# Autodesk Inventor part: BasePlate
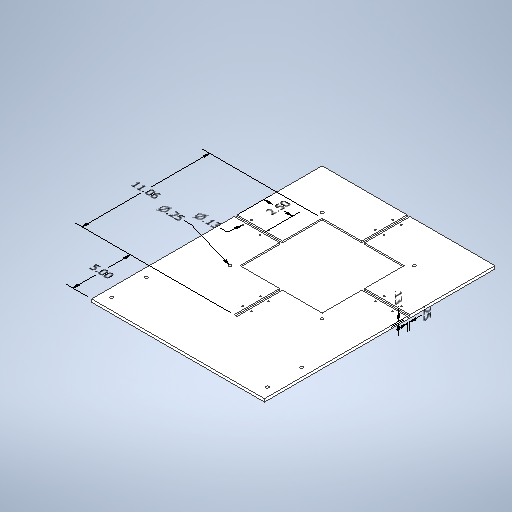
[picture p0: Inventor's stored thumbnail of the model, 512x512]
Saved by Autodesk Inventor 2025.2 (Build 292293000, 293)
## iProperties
Created: 2025-09
Part Number: BasePlate
Material: Generic
Document SubType Name: Modeling
Designer: tyler
Density: 1 g/cm^3
Appearance: Default
Author: tyler
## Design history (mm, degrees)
node "Annotations"
  node "Diameter Dimension 1" dims "d8" = 381, "d9" = 381, "d10" = 180.975, "d11" = 180.975, "d12" = 3.175, "d13" = 3.175, "d22" = 360 deg (derived), "d50" = 6.35 (derived)
  node "Diameter Dimension 2" dims "d8" = 381, "d9" = 381, "d10" = 180.975, "d11" = 180.975, "d12" = 3.175, "d13" = 3.175, "d22" = 360 deg (derived), "d52" = 3.175 (derived)
  node "Linear Dimension 1" dims "d8" = 381, "d9" = 381, "d10" = 180.975, "d11" = 180.975, "d12" = 3.175, "d13" = 3.175, "d22" = 360 deg (derived), "d55" = 3.175 (derived)
  node "Linear Dimension 2" dims "d8" = 381, "d9" = 381, "d10" = 180.975, "d11" = 180.975, "d12" = 3.175, "d13" = 3.175, "d22" = 360 deg (derived), "d58" = 6.35 (derived)
  node "Linear Dimension 3" dims "d8" = 381, "d9" = 381, "d10" = 180.975, "d11" = 180.975, "d12" = 3.175, "d13" = 3.175, "d22" = 360 deg (derived), "d60" = 63.5 (derived)
  node "Linear Dimension 4" dims "d8" = 381, "d9" = 381, "d10" = 180.975, "d11" = 180.975, "d12" = 3.175, "d13" = 3.175, "d22" = 360 deg (derived), "d74" = 127 (derived)
  node "Linear Dimension 5" dims "d8" = 381, "d9" = 381, "d10" = 180.975, "d11" = 180.975, "d12" = 3.175, "d13" = 3.175, "d22" = 360 deg (derived), "d78" = 280.9875 (derived)
sketch "Sketch1"
  geometry: L1 (190.5, 254)-(-190.5, 254); L2 (-190.5, 254)-(-190.5, -254); L3 (-190.5, -254)-(190.5, -254); L4 (190.5, -254)-(190.5, 254); L5 (190.5, 254)-(-190.5, -254); L6 (-190.5, 254)-(190.5, -254); L7 (-190.5, -254)-(190.5, -254); L8 (190.5, -254)-(190.5, 127); L9 (-190.5, 127)-(-190.5, -254); L10 (88.9, -152.4)-(-88.9, -152.4); L11 (-88.9, -152.4)-(-88.9, 25.4); L12 (-88.9, 25.4)-(88.9, -152.4); L13 (88.9, 25.4)-(-88.9, -152.4); 2 further points
  constraints: 26 end point, 4 midpoint, 3 parallel, 2 horizontal, 2 perpendicular
  dimensions: "d0" = 381 distance of L3.end L2.end; "d1" = 508 distance of L2.end L1.end; "d3" = 381 distance of L8.end L7.end
extrude "Extrusion1" new body sketch "Sketch1" distance "d6" = 6.35; taper "d7" = 0 deg
sketch "Sketch2"
  geometry: L1 (190.5, -254)-(190.5, 254) reference; L2 (190.5, 254)-(-190.5, 254); L3 (-190.5, 254)-(-190.5, -127); L4 (-190.5, -127)-(190.5, -127); L5 (190.5, -127)-(190.5, 254); L6 (-190.5, 254)-(-190.5, 63.5); L7 (90.487, -26.988)-(-90.487, -26.988); L8 (-90.487, -26.988)-(-90.487, 153.987); L9 (-90.487, 153.987)-(90.487, 153.987); L10 (90.487, 153.987)-(90.487, -26.988); L11 (90.487, -26.988)-(-90.487, 153.987); L12 (-90.487, -26.988)-(90.487, 153.987); L13 (-90.487, 63.5)-(-90.487, 66.675); L14 (-90.487, 63.5)-(-90.487, 60.325); L15 (-90.487, 60.325)-(-190.5, 60.325); L16 (-90.487, 63.5)-(-190.5, 63.5); L17 (-90.487, 66.675)-(-190.5, 66.675); L18 (3.175, -26.988)-(3.175, -127); L19 (-3.175, -26.988)-(-3.175, -127); L20 (90.487, 66.675)-(190.5, 66.675); L21 (90.487, 60.325)-(190.5, 60.325); L22 (-3.175, 153.987)-(-3.175, 254); L23 (3.175, 153.987)-(3.175, 254); 16 further points
  constraints: 44 end point, 5 perpendicular, 4 midpoint, 4 parallel, 4 point on line, 2 horizontal, 25 other
  dimensions: "d8" = 381 distance of L4.end L3.end; "d9" = 381 distance of L3.end L2.end; "d10" = 180.975 distance of L8.end L9.end; "d11" = 180.975 distance of L7.end L8.end; "d12" = 3.175 distance of L13.start L13.end; "d13" = 3.175 distance of L13.start L14.end; "d22" = 360 deg dimension on point (0, 63.5) L14.end (derived)
extrude "Extrusion2" cut sketch "Sketch2" distance "d18" = 3.175; taper "d19" = 0 deg
sketch "Sketch3" dims "d28" = 12.7
  geometry: L1 (-190.5, 60.325)-(-190.5, 66.675) reference; L2 (-190.5, 63.5)-(0, 63.5); L3 (101.6, 165.1)-(-101.6, 165.1); L4 (-101.6, 165.1)-(-101.6, -38.1); L5 (-101.6, -38.1)-(101.6, -38.1); L6 (101.6, -38.1)-(101.6, 165.1); L7 (101.6, 165.1)-(-101.6, -38.1); L8 (-101.6, 165.1)-(101.6, -38.1); L9 (-107.95, -38.1)-(-107.95, 165.1); L10 (-101.6, 171.45)-(101.6, 171.45); L11 (107.95, 165.1)-(107.95, -38.1); L12 (101.6, -44.45)-(-101.6, -44.45); L13 (-107.95, 60.325)-(-120.65, 60.325); L14 (-90.487, 60.325)-(-190.5, 60.325) reference; L15 (-120.65, 60.325)-(-171.45, 60.325); L16 (-171.45, 60.325)-(-171.45, 47.625); L17 (-171.45, 47.625)-(-120.65, 47.625); L18 (-120.65, 47.625)-(-120.65, 60.325); L19 (-120.65, 66.675)-(-171.45, 66.675); L20 (-171.45, 66.675)-(-171.45, 79.375); L21 (-171.45, 79.375)-(-120.65, 79.375); L22 (-120.65, 79.375)-(-120.65, 66.675); L23 (-120.65, 60.325)-(-133.35, 47.625); L24 (-171.45, 60.325)-(-158.75, 47.625); L25 (-120.65, 66.675)-(-133.35, 79.375); L26 (-171.45, 66.675)-(-158.75, 79.375); C1 r 1.587 at (-127, 53.975); C2 r 1.587 at (-165.1, 53.975); C3 r 1.587 at (-127, 73.025); C4 r 1.587 at (-165.1, 73.025); C5 r 3.175 at (101.6, -38.1); C6 r 3.175 at (-101.6, -38.1); C7 r 3.175 at (-101.6, 165.1); C8 r 3.175 at (101.6, 165.1); C9 r 1.587 at (9.525, -63.5); C10 r 1.587 at (-9.525, -63.5); C11 r 1.587 at (-9.525, -101.6); C12 r 1.587 at (9.525, -101.6); C13 r 1.587 at (127, 73.025); C14 r 1.587 at (127, 53.975); C15 r 1.587 at (165.1, 53.975); C16 r 1.587 at (165.1, 73.025); C17 r 1.587 at (-9.525, 190.5); C18 r 1.587 at (9.525, 190.5); C19 r 1.587 at (9.525, 228.6); C20 r 1.587 at (-9.525, 228.6); A1 r 6.35 centre (-101.6, -38.1) between (-107.95, -38.1) and (-101.6, -44.45); A2 r 6.35 centre (-101.6, 165.1) between (-107.95, 165.1) and (-101.6, 171.45); A3 r 6.35 centre (101.6, -38.1) between (107.95, -38.1) and (101.6, -44.45); 2 further points
  constraints: 48 end point, 23 centre point, 8 coincident, 8 parallel, 8 point on line, 7 midpoint, 6 point on circle, 5 horizontal, 4 perpendicular, 2 tangent, 1 vertical alignment, 35 other
  dimensions: "d24" = 203.2 distance of L5.end L4.end; "d25" = 203.2 distance of L4.end L3.end; "d26" = 12.7 diameter of A1; "d27" = 12.7 diameter of A2; "d29" = 12.7 diameter of A3; "d30" = 12.7 distance of L13.start L13.end; "d31" = 50.8 distance of L17.end L16.end; "d32" = 12.7 distance of L16.end L15.end; "d33" = 50.8 distance of L20.end L21.end; "d34" = 12.7 distance of L19.end L20.end; "d35" = 3.175 diameter of C1; "d36" = 3.175 diameter of C2; "d37" = 3.175 diameter of C3; "d38" = 3.175 diameter of C4; "d39" = 6.35 diameter of C5; "d40" = 6.35 diameter of C6; "d41" = 6.35 diameter of C7; "d42" = 6.35 diameter of C8; "d45" = 360 deg dimension on L2.end C1.centre (derived)
extrude "Extrusion3" cut sketch "Sketch3" distance "d47" = 6.35; taper "d48" = 0 deg
sketch "Sketch4"
  geometry: L1 (-190.5, 254)-(-190.5, -254) reference; L2 (-190.5, -254)-(-190.5, -247.65); L3 (-190.5, -247.65)-(-184.15, -247.65); L4 (-184.15, -247.65)-(-184.15, -52.726); L5 (-184.15, -247.65)-(0, -247.65); L6 (0, -247.65)-(0, -127.291); L7 (-184.15, -247.65)-(-184.15, -228.6); L8 (-184.15, -228.6)-(-171.45, -228.6); L9 (-184.15, -228.6)-(-184.15, -187.96); L10 (-184.15, -127.291)-(-184.15, -152.691); L11 (-184.15, -152.691)-(-171.45, -152.691); L12 (-190.5, -254)-(190.5, -254) reference; C1 r 3.175 at (-171.45, -228.6); C2 r 3.175 at (-171.45, -152.691); C3 r 3.175 at (171.45, -228.6); C4 r 3.175 at (171.45, -152.691); 1 further point
  constraints: 20 end point, 5 perpendicular, 5 point on line, 4 centre point, 2 coincident, 2 symmetric about line, 1 horizontal, 2 other
  dimensions: "d61" = 6.35 distance of L1.end L2.end; "d62" = 6.35 distance of L2.end L3.end; "d63" = 19.05 distance of L3.end L7.end; "d64" = 12.7 distance of L7.end L8.end; "d67" = 25.4 distance of L10.start L10.end; "d68" = 6.35 diameter of C1; "d69" = 6.35 diameter of C2; "d75" = 25.4 distance from line of L12 C3.centre (derived)
extrude "Extrusion4" cut sketch "Sketch4" distance "d70" = 25.4; taper "d71" = 0 deg
body "Solid1"
node "Sketch Circular Pattern2" dims "d22" = 360 deg (derived)
node "Sketch Circular Pattern3" dims "d45" = 360 deg (derived)
other parameters: "d49" = 0.10935 (derived), "d51" = 61.46914 (derived), "d53" = 0 (derived), "d56" = 0 (derived), "d59" = 0.22465 (derived), "d72" = 5.48061 (derived), "d73" = 4.95383 (derived), "d76" = 5.60121 (derived), "d77" = 8.48137 (derived)
